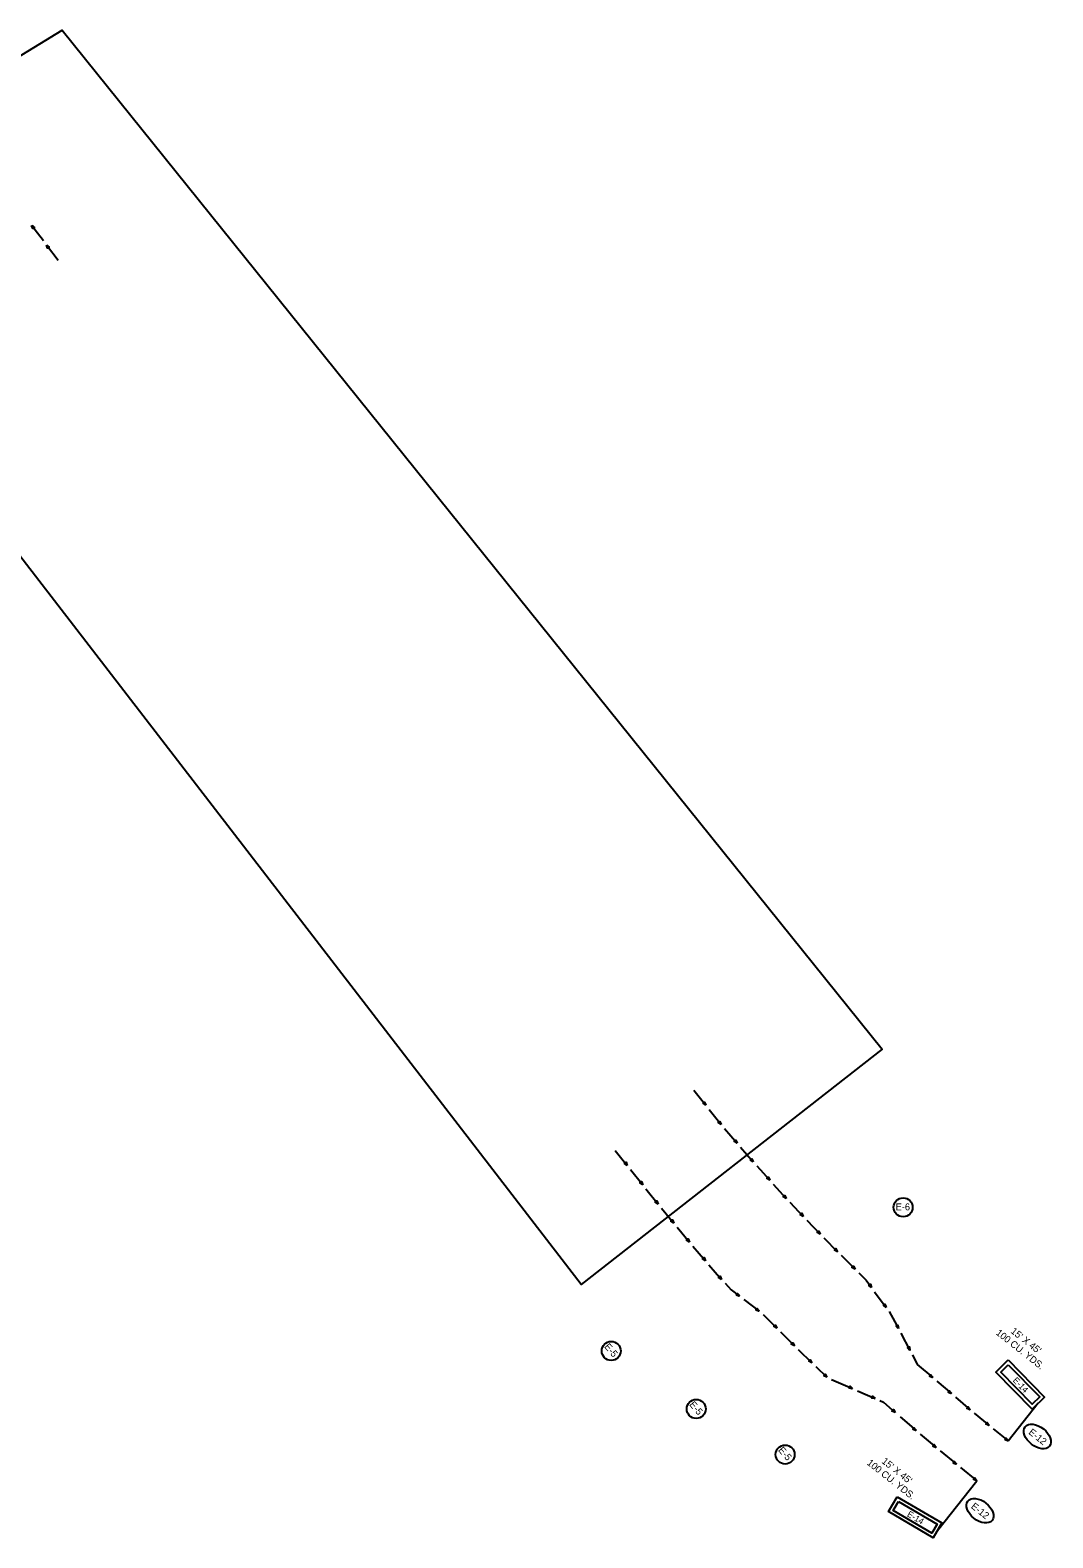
# Model space of a CAD drawing. Extents: x 881727 to 890277, y 1562105 to 1567179.
# Drawn here: x 883800 to 884689, y 1564822 to 1566132 of the extents above; entities that cross this region are included whole.
import ezdxf

# ---------------------------------------------------------------- set-up
doc = ezdxf.new("R2010")
doc.units = 0
for name, color, linetype in [('22', 7, 'Continuous'), ('R_Axis', 7, 'Continuous'), ('R_Proposed Const Limits_Cut', 7, 'Continuous'), ('R_Water', 7, 'Continuous')]:
    doc.layers.add(name, color=color, linetype=linetype)

msp = doc.modelspace()

# ---------------------------------------------------------------- linework, layer by layer
at = {"layer": '22'}
msp.add_lwpolyline([(883563.3, 1565970.3), (883827.9, 1566132), (884540.8, 1565246.7), (884279.1, 1565042.3)], close=True, dxfattribs=at)
for centre in [(884305.2, 1564984.5), (884379.1, 1564934.1), (884456.4, 1564894.5)]:
    msp.add_circle(centre, 8.26, dxfattribs=at)
at = {"layer": 'R_Proposed Const Limits_Cut'}
for p, q in [((883802.5, 1565959.7), (883801.6, 1565961.7)), ((883802.9, 1565960), (883801.7, 1565961.8)), ((883802.7, 1565959.9), (883801.7, 1565961.8)), ((883803.2, 1565960.3), (883801.8, 1565961.9)), ((883803.6, 1565960.5), (883801.9, 1565961.9)), ((883803.4, 1565960.4), (883801.9, 1565961.9)), ((883815.4, 1565942.6), (883814.5, 1565944.6)), ((883815.7, 1565942.9), (883814.6, 1565944.7)), ((883815.6, 1565942.8), (883814.6, 1565944.6)), ((883816.3, 1565943.3), (883814.7, 1565944.8)), ((883816.1, 1565943.2), (883814.7, 1565944.7)), ((883816.5, 1565943.4), (883814.8, 1565944.8)), ((884385.1, 1565199.8), (884386.8, 1565198.4)), ((884385.3, 1565199.9), (884386.9, 1565198.5)), ((884385.5, 1565200.1), (884386.9, 1565198.5)), ((884385.8, 1565200.4), (884387, 1565198.6)), ((884386, 1565200.5), (884387.1, 1565198.6)), ((884386.2, 1565200.6), (884387.1, 1565198.7)), ((884398.5, 1565183.1), (884400.2, 1565181.7)), ((884398.7, 1565183.2), (884400.3, 1565181.8)), ((884398.9, 1565183.4), (884400.3, 1565181.8)), ((884399.2, 1565183.6), (884400.4, 1565181.9)), ((884399.4, 1565183.8), (884400.4, 1565181.9)), ((884399.5, 1565183.9), (884400.5, 1565181.9)), ((884412.3, 1565166.7), (884414.1, 1565165.4)), ((884412.5, 1565166.8), (884414.1, 1565165.5)), ((884412.7, 1565167), (884414.2, 1565165.5)), ((884413, 1565167.3), (884414.3, 1565165.6)), ((884413.2, 1565167.4), (884414.3, 1565165.6)), ((884413.3, 1565167.6), (884414.4, 1565165.6)), ((884316.9, 1565147.4), (884318.6, 1565146.1)), ((884317.1, 1565147.6), (884318.6, 1565146.1)), ((884317.2, 1565147.7), (884318.7, 1565146.1)), ((884317.6, 1565148), (884318.8, 1565146.2)), ((884317.8, 1565148.1), (884318.8, 1565146.2)), ((884317.9, 1565148.2), (884318.9, 1565146.3)), ((884426.3, 1565150.5), (884428.1, 1565149.2)), ((884426.5, 1565150.6), (884428.1, 1565149.2)), ((884426.7, 1565150.8), (884428.2, 1565149.3)), ((884427, 1565151.1), (884428.2, 1565149.3)), ((884427.2, 1565151.2), (884428.3, 1565149.4)), ((884427.3, 1565151.3), (884428.3, 1565149.4)), ((884440.6, 1565134.5), (884442.4, 1565133.3)), ((884440.8, 1565134.7), (884442.4, 1565133.3)), ((884440.9, 1565134.8), (884442.5, 1565133.4)), ((884441.3, 1565135.1), (884442.6, 1565133.4)), ((884441.4, 1565135.3), (884442.6, 1565133.5)), ((884441.6, 1565135.4), (884442.7, 1565133.5)), ((884330.3, 1565130.7), (884332, 1565129.3)), ((884330.4, 1565130.8), (884332, 1565129.4)), ((884330.6, 1565131), (884332.1, 1565129.4)), ((884331, 1565131.2), (884332.1, 1565129.5)), ((884331.1, 1565131.4), (884332.2, 1565129.5)), ((884331.3, 1565131.5), (884332.2, 1565129.5)), ((884455.7, 1565119.2), (884457, 1565117.6)), ((884455.8, 1565119.4), (884457, 1565117.6)), ((884456, 1565119.5), (884457.1, 1565117.6)), ((884343.7, 1565114), (884345.4, 1565112.6)), ((884343.8, 1565114.1), (884345.4, 1565112.7)), ((884344, 1565114.3), (884345.5, 1565112.7)), ((884344.4, 1565114.5), (884345.6, 1565112.8)), ((884344.5, 1565114.7), (884345.6, 1565112.8)), ((884344.7, 1565114.8), (884345.7, 1565112.8)), ((884455, 1565118.6), (884456.8, 1565117.4)), ((884455.2, 1565118.8), (884456.8, 1565117.4)), ((884455.3, 1565118.9), (884456.9, 1565117.5)), ((884357.2, 1565097.4), (884359, 1565096.1)), ((884357.4, 1565097.5), (884359, 1565096.1)), ((884357.6, 1565097.7), (884359, 1565096.1)), ((884357.9, 1565098), (884359.1, 1565096.2)), ((884358.1, 1565098.1), (884359.2, 1565096.2)), ((884358.3, 1565098.2), (884359.2, 1565096.3)), ((884469.7, 1565103), (884471.5, 1565101.8)), ((884469.9, 1565103.2), (884471.5, 1565101.9)), ((884470, 1565103.3), (884471.6, 1565101.9)), ((884470.3, 1565103.6), (884471.7, 1565102)), ((884470.5, 1565103.8), (884471.7, 1565102)), ((884470.7, 1565104), (884471.8, 1565102.1)), ((884370.9, 1565080.9), (884372.6, 1565079.5)), ((884371, 1565081), (884372.6, 1565079.6)), ((884371.2, 1565081.2), (884372.7, 1565079.6)), ((884371.6, 1565081.4), (884372.8, 1565079.7)), ((884371.7, 1565081.6), (884372.8, 1565079.7)), ((884371.9, 1565081.7), (884372.9, 1565079.8)), ((884484.5, 1565087.5), (884486.3, 1565086.3)), ((884484.6, 1565087.7), (884486.3, 1565086.4)), ((884484.8, 1565087.8), (884486.4, 1565086.4)), ((884485.1, 1565088.1), (884486.4, 1565086.5)), ((884485.3, 1565088.3), (884486.5, 1565086.5)), ((884485.4, 1565088.4), (884486.5, 1565086.6)), ((884499.5, 1565072.3), (884501.4, 1565071.1)), ((884499.7, 1565072.5), (884501.4, 1565071.2)), ((884499.8, 1565072.6), (884501.5, 1565071.2)), ((884500.2, 1565072.9), (884501.5, 1565071.3)), ((884500.3, 1565073.1), (884501.6, 1565071.4)), ((884500.5, 1565073.2), (884501.6, 1565071.4)), ((884384.8, 1565064.6), (884386.6, 1565063.3)), ((884385, 1565064.7), (884386.6, 1565063.3)), ((884385.1, 1565064.9), (884386.6, 1565063.4)), ((884385.5, 1565065.2), (884386.7, 1565063.5)), ((884385.6, 1565065.3), (884386.8, 1565063.5)), ((884385.8, 1565065.5), (884386.8, 1565063.5)), ((884514.7, 1565057.2), (884516.5, 1565056)), ((884514.8, 1565057.3), (884516.6, 1565056.1)), ((884515, 1565057.5), (884516.6, 1565056.1)), ((884515.3, 1565057.8), (884516.7, 1565056.2)), ((884515.5, 1565057.9), (884516.7, 1565056.2)), ((884515.6, 1565058.1), (884516.8, 1565056.3)), ((884398.8, 1565048.4), (884400.6, 1565047.1)), ((884399, 1565048.5), (884400.6, 1565047.2)), ((884399.2, 1565048.7), (884400.7, 1565047.2)), ((884399.5, 1565049), (884400.8, 1565047.3)), ((884399.7, 1565049.1), (884400.8, 1565047.3)), ((884399.8, 1565049.3), (884400.8, 1565047.3)), ((884529.3, 1565041.6), (884530.9, 1565040.2)), ((884529.4, 1565041.7), (884531, 1565040.2)), ((884529.6, 1565041.9), (884531, 1565040.3)), ((884530, 1565042.1), (884531.1, 1565040.3)), ((884530.2, 1565042.3), (884531.1, 1565040.4)), ((884530.3, 1565042.4), (884531.2, 1565040.4)), ((884414.1, 1565033.2), (884416.1, 1565032.3)), ((884414.2, 1565033.4), (884416.1, 1565032.4)), ((884414.4, 1565033.6), (884416.2, 1565032.4)), ((884414.7, 1565033.9), (884416.2, 1565032.5)), ((884414.8, 1565034.1), (884416.3, 1565032.6)), ((884414.9, 1565034.3), (884416.3, 1565032.6)), ((884431.2, 1565020.3), (884433.2, 1565019.4)), ((884431.3, 1565020.5), (884433.2, 1565019.4)), ((884431.4, 1565020.6), (884433.2, 1565019.5)), ((884431.7, 1565021), (884433.3, 1565019.6)), ((884431.8, 1565021.2), (884433.3, 1565019.6)), ((884432, 1565021.3), (884433.4, 1565019.7)), ((884542, 1565024.4), (884543.6, 1565022.9)), ((884542.1, 1565024.5), (884543.7, 1565023)), ((884542.3, 1565024.6), (884543.7, 1565023)), ((884542.7, 1565024.9), (884543.8, 1565023.1)), ((884542.8, 1565025), (884543.8, 1565023.1)), ((884543, 1565025.1), (884543.9, 1565023.1)), ((884446.8, 1565005.8), (884448.6, 1565004.7)), ((884447, 1565006), (884448.7, 1565004.7)), ((884447.1, 1565006.1), (884448.7, 1565004.8)), ((884447.4, 1565006.5), (884448.8, 1565004.8)), ((884447.6, 1565006.6), (884448.8, 1565004.9)), ((884447.7, 1565006.8), (884448.9, 1565004.9)), ((884553, 1565006.2), (884554.4, 1565004.5)), ((884553.2, 1565006.3), (884554.5, 1565004.6)), ((884553.4, 1565006.4), (884554.5, 1565004.6)), ((884553.8, 1565006.6), (884554.6, 1565004.6)), ((884554, 1565006.7), (884554.7, 1565004.7)), ((884554.2, 1565006.8), (884554.7, 1565004.7)), ((884461.9, 1564990.6), (884463.7, 1564989.4)), ((884462, 1564990.8), (884463.7, 1564989.5)), ((884462.2, 1564990.9), (884463.8, 1564989.5)), ((884462.5, 1564991.2), (884463.9, 1564989.6)), ((884462.7, 1564991.4), (884463.9, 1564989.7)), ((884462.8, 1564991.5), (884464, 1564989.7)), ((884477.2, 1564975.6), (884479.1, 1564974.5)), ((884477.4, 1564975.8), (884479.1, 1564974.6)), ((884477.5, 1564976), (884479.1, 1564974.6)), ((884477.8, 1564976.3), (884479.2, 1564974.7)), ((884478, 1564976.4), (884479.3, 1564974.7)), ((884478.1, 1564976.6), (884479.3, 1564974.8)), ((884563, 1564987.2), (884564.4, 1564985.6)), ((884563.2, 1564987.3), (884564.5, 1564985.6)), ((884563.4, 1564987.4), (884564.5, 1564985.7)), ((884563.8, 1564987.7), (884564.6, 1564985.7)), ((884564, 1564987.8), (884564.7, 1564985.7)), ((884564.2, 1564987.9), (884564.7, 1564985.7)), ((884490.2, 1564963.1), (884492.1, 1564962)), ((884490.3, 1564963.3), (884492.1, 1564962)), ((884490.5, 1564963.4), (884492.1, 1564962.1)), ((884490.8, 1564963.8), (884492.2, 1564962.2)), ((884490.9, 1564963.9), (884492.2, 1564962.2)), ((884491.1, 1564964.1), (884492.3, 1564962.2)), ((884582.1, 1564962.7), (884584.1, 1564961.7)), ((884582.3, 1564962.9), (884584.1, 1564961.7)), ((884582.4, 1564963), (884584.1, 1564961.8)), ((884582.7, 1564963.4), (884584.2, 1564961.9)), ((884582.9, 1564963.5), (884584.3, 1564961.9)), ((884583, 1564963.7), (884584.3, 1564962)), ((884512.2, 1564952.4), (884514.3, 1564952)), ((884512.3, 1564952.6), (884514.3, 1564952)), ((884512.4, 1564952.8), (884514.4, 1564952.1)), ((884512.5, 1564953.2), (884514.4, 1564952.2)), ((884512.6, 1564953.4), (884514.4, 1564952.2)), ((884512.7, 1564953.6), (884514.5, 1564952.3)), ((884598.4, 1564948.7), (884600.3, 1564947.7)), ((884598.5, 1564948.9), (884600.3, 1564947.8)), ((884598.7, 1564949.1), (884600.4, 1564947.8)), ((884599, 1564949.4), (884600.5, 1564947.9)), ((884599.1, 1564949.6), (884600.5, 1564948)), ((884599.2, 1564949.7), (884600.5, 1564948)), ((884531.8, 1564943.8), (884534, 1564943.4)), ((884531.9, 1564944), (884534, 1564943.4)), ((884532, 1564944.2), (884534, 1564943.5)), ((884532.2, 1564944.8), (884534.1, 1564943.6)), ((884532.2, 1564944.6), (884534, 1564943.6)), ((884532.3, 1564945), (884534.1, 1564943.7)), ((884615.3, 1564935.6), (884616.7, 1564934)), ((884615.5, 1564935.8), (884616.8, 1564934)), ((884650.4, 1564906.3), (884676.5, 1564939.3)), ((884549.5, 1564932.5), (884551.4, 1564931.5)), ((884549.6, 1564932.7), (884551.4, 1564931.5)), ((884549.8, 1564932.8), (884551.5, 1564931.6)), ((884550.1, 1564933.2), (884551.5, 1564931.6)), ((884550.2, 1564933.3), (884551.6, 1564931.7)), ((884550.4, 1564933.5), (884551.6, 1564931.7)), ((884614.6, 1564934.8), (884616.5, 1564933.7)), ((884614.7, 1564934.9), (884616.6, 1564933.8)), ((884614.9, 1564935.1), (884616.6, 1564933.8)), ((884615.2, 1564935.4), (884616.7, 1564933.9)), ((884567.7, 1564916.6), (884569.6, 1564915.6)), ((884567.8, 1564916.8), (884569.6, 1564915.7)), ((884568, 1564917), (884569.7, 1564915.7)), ((884568.3, 1564917.3), (884569.8, 1564915.8)), ((884568.4, 1564917.5), (884569.8, 1564915.8)), ((884568.5, 1564917.6), (884569.8, 1564915.9)), ((884631.1, 1564921.1), (884633, 1564920.1)), ((884631.2, 1564921.2), (884633.1, 1564920.2)), ((884631.4, 1564921.4), (884633.1, 1564920.2)), ((884631.7, 1564921.8), (884633.2, 1564920.3)), ((884631.8, 1564921.9), (884633.2, 1564920.3)), ((884631.9, 1564922.1), (884633.3, 1564920.4)), ((884585.1, 1564901.9), (884587, 1564900.9)), ((884585.2, 1564902.1), (884587, 1564900.9)), ((884585.3, 1564902.2), (884587.1, 1564901)), ((884585.6, 1564902.6), (884587.1, 1564901.1)), ((884585.8, 1564902.7), (884587.2, 1564901.1)), ((884585.9, 1564902.9), (884587.2, 1564901.2)), ((884647.7, 1564907.6), (884649.7, 1564906.6)), ((884647.9, 1564907.7), (884649.7, 1564906.7)), ((884648, 1564907.9), (884649.7, 1564906.7)), ((884648.3, 1564908.3), (884649.8, 1564906.8)), ((884648.4, 1564908.4), (884649.9, 1564906.8)), ((884648.6, 1564908.6), (884649.9, 1564906.9)), ((884602.6, 1564887.4), (884604.6, 1564886.4)), ((884602.8, 1564887.5), (884604.6, 1564886.4)), ((884602.9, 1564887.7), (884604.6, 1564886.5)), ((884603.2, 1564888.1), (884604.7, 1564886.6)), ((884603.3, 1564888.2), (884604.8, 1564886.6)), ((884603.5, 1564888.4), (884604.8, 1564886.7)), ((884588.8, 1564828.6), (884623, 1564871.8)), ((884620.4, 1564873.1), (884622.3, 1564872.1)), ((884620.5, 1564873.2), (884622.4, 1564872.2)), ((884620.6, 1564873.4), (884622.4, 1564872.2)), ((884620.9, 1564873.8), (884622.5, 1564872.3)), ((884621.1, 1564873.9), (884622.5, 1564872.3)), ((884621.2, 1564874.1), (884622.6, 1564872.4))]:
    msp.add_line(p, q, dxfattribs=at)
for points in [[(883811.5, 1565948.9), (883801.3, 1565962.4)], [(883824.4, 1565931.8), (883814.2, 1565945.3)], [(884376.9, 1565211.2), (884387.4, 1565198)], [(884390.3, 1565194.4), (884400.8, 1565181.2)], [(884403.7, 1565177.8), (884414.7, 1565165)], [(884308.7, 1565158.8), (884319.2, 1565145.6)], [(884417.7, 1565161.5), (884428.7, 1565148.7)], [(884431.7, 1565145.4), (884443, 1565132.8)], [(884322, 1565142.1), (884332.6, 1565128.8)], [(884335.4, 1565125.4), (884346, 1565112.1)], [(884446.1, 1565129.5), (884457.4, 1565117)], [(884348.8, 1565108.6), (884359.6, 1565095.6)], [(884460.5, 1565113.7), (884472.2, 1565101.4)], [(884475.3, 1565098.2), (884486.9, 1565085.9)], [(884362.4, 1565092.1), (884373.2, 1565079.1)], [(884490.1, 1565082.7), (884502, 1565070.7)], [(884376.1, 1565075.6), (884387.2, 1565062.8)], [(884505.2, 1565067.6), (884517.2, 1565055.6)], [(884390.1, 1565059.4), (884401.2, 1565046.7)], [(884404.2, 1565043.3), (884409.6, 1565037.6)], [(884520.4, 1565052.5), (884526.9, 1565046.1)], [(884526.9, 1565046.1), (884531.5, 1565039.7)], [(884409.6, 1565037.6), (884416.8, 1565032)], [(884420.4, 1565029.3), (884433.9, 1565019.1)], [(884534.1, 1565036), (884544.2, 1565022.4)], [(884437.4, 1565016.3), (884449.3, 1565004.3)], [(884546.9, 1565018.8), (884554.9, 1565003.9)], [(884452.5, 1565001.1), (884464.4, 1564989)], [(884557, 1565000), (884564.9, 1564985)], [(884467.6, 1564985.9), (884479.7, 1564974.1)], [(884567, 1564981), (884571.3, 1564972.8)], [(884483, 1564971), (884492.7, 1564961.6)], [(884571.3, 1564972.8), (884584.8, 1564961.3)], [(884496.8, 1564959.8), (884515.1, 1564951.8)], [(884519.2, 1564950), (884534.7, 1564943.2)], [(884588.2, 1564958.4), (884601, 1564947.4)], [(884538.8, 1564941.4), (884542, 1564940)], [(884542, 1564940), (884552.1, 1564931.1)], [(884604.4, 1564944.4), (884617.2, 1564933.4)], [(884556.5, 1564927.2), (884570.3, 1564915.3)], [(884620.7, 1564930.5), (884633.7, 1564919.8)], [(884573.7, 1564912.3), (884587.7, 1564900.5)], [(884637.2, 1564916.9), (884650.4, 1564906.3)], [(884591.1, 1564897.7), (884605.3, 1564886.1)], [(884608.8, 1564883.2), (884623, 1564871.8)]]:
    msp.add_lwpolyline(points, dxfattribs=at)
for points in [[(883801.3, 1565962.4), (883803.8, 1565960.7), (883802.3, 1565959.6)], [(883814.2, 1565945.3), (883816.6, 1565943.6), (883815.2, 1565942.5)], [(884387.4, 1565198), (884385, 1565199.7), (884386.3, 1565200.8)], [(884400.8, 1565181.2), (884398.3, 1565182.9), (884399.7, 1565184)], [(884414.7, 1565165), (884412.2, 1565166.6), (884413.5, 1565167.7)], [(884319.2, 1565145.6), (884316.7, 1565147.3), (884318.1, 1565148.4)], [(884428.7, 1565148.7), (884426.2, 1565150.3), (884427.5, 1565151.5)], [(884443, 1565132.8), (884440.5, 1565134.4), (884441.8, 1565135.6)], [(884332.6, 1565128.8), (884330.1, 1565130.5), (884331.5, 1565131.6)], [(884457.4, 1565117), (884454.8, 1565118.5), (884456.1, 1565119.7)], [(884346, 1565112.1), (884343.5, 1565113.8), (884344.9, 1565115)], [(884359.6, 1565095.6), (884357.1, 1565097.2), (884358.4, 1565098.4)], [(884472.2, 1565101.4), (884469.5, 1565102.9), (884470.8, 1565104.1)], [(884373.2, 1565079.1), (884370.7, 1565080.7), (884372.1, 1565081.9)], [(884486.9, 1565085.9), (884484.3, 1565087.4), (884485.6, 1565088.6)], [(884502, 1565070.7), (884499.4, 1565072.1), (884500.6, 1565073.4)], [(884387.2, 1565062.8), (884384.6, 1565064.4), (884386, 1565065.6)], [(884517.2, 1565055.6), (884514.5, 1565057), (884515.8, 1565058.3)], [(884401.2, 1565046.7), (884398.6, 1565048.2), (884400, 1565049.4)], [(884531.5, 1565039.7), (884529.1, 1565041.5), (884530.5, 1565042.5)], [(884416.8, 1565032), (884414, 1565033.1), (884415.1, 1565034.5)], [(884433.9, 1565019.1), (884431, 1565020.1), (884432.1, 1565021.5)], [(884544.2, 1565022.4), (884541.8, 1565024.2), (884543.2, 1565025.3)], [(884449.3, 1565004.3), (884446.6, 1565005.7), (884447.9, 1565006.9)], [(884554.9, 1565003.9), (884552.8, 1565006.1), (884554.3, 1565006.9)], [(884464.4, 1564989), (884461.7, 1564990.5), (884463, 1564991.7)], [(884479.7, 1564974.1), (884477, 1564975.5), (884478.3, 1564976.8)], [(884564.9, 1564985), (884562.8, 1564987.1), (884564.4, 1564988)], [(884492.7, 1564961.6), (884490, 1564963), (884491.3, 1564964.2)], [(884584.8, 1564961.3), (884582, 1564962.5), (884583.2, 1564963.9)], [(884515.1, 1564951.8), (884512.1, 1564952.2), (884512.8, 1564953.8)], [(884601, 1564947.4), (884598.2, 1564948.6), (884599.4, 1564949.9)], [(884534.7, 1564943.2), (884531.7, 1564943.6), (884532.4, 1564945.2)], [(884617.2, 1564933.4), (884614.5, 1564934.6), (884615.6, 1564935.9)], [(884552.1, 1564931.1), (884549.3, 1564932.3), (884550.5, 1564933.7)], [(884570.3, 1564915.3), (884567.5, 1564916.5), (884568.7, 1564917.8)], [(884633.7, 1564919.8), (884630.9, 1564920.9), (884632.1, 1564922.3)], [(884587.7, 1564900.5), (884584.9, 1564901.7), (884586.1, 1564903.1)], [(884650.4, 1564906.3), (884647.6, 1564907.4), (884648.7, 1564908.8)], [(884605.3, 1564886.1), (884602.5, 1564887.2), (884603.6, 1564888.6)], [(884623, 1564871.8), (884620.2, 1564872.9), (884621.3, 1564874.3)]]:
    msp.add_lwpolyline(points, close=True, dxfattribs=at)
for centre in [(884675.7, 1564910.2), (884625.8, 1564845.7)]:
    msp.add_ellipse(centre, major_axis=(10.6, -8.4), ratio=0.622952, dxfattribs=at)
at = {"layer": 'R_Water'}
for points in [[(884650.4, 1564976.7), (884681.9, 1564944.5), (884671.2, 1564934), (884639.7, 1564966.2)], [(884650.4, 1564972.5), (884677.7, 1564944.6), (884671.2, 1564938.3), (884644, 1564966.2)], [(884553.8, 1564857.9), (884592.6, 1564835.1), (884585, 1564822.1), (884546.2, 1564844.9)], [(884554.9, 1564853.7), (884588.5, 1564834), (884583.9, 1564826.2), (884550.3, 1564846)]]:
    msp.add_lwpolyline(points, close=True, dxfattribs=at)
for centre in [(884559, 1565109.3), (884305.2, 1564984.5), (884379.1, 1564934.1), (884456.4, 1564894.5)]:
    msp.add_circle(centre, 8.26, dxfattribs=at)

# ---------------------------------------------------------------- texts
at = {"layer": 'R_Axis'}
for s, p in [('100 CU. YDS.', (884639.1, 1564999.3)), ("15' X 45'", (884652, 1565000.7)), ('100 CU. YDS.', (884527, 1564886.3)), ("15' X 45'", (884539.8, 1564887.7))]:
    msp.add_text(s, height=6, rotation=321.5971, dxfattribs=at).set_placement(p)
at = {"layer": 'R_Proposed Const Limits_Cut'}
for p in [(884667.5, 1564912.9), (884617.5, 1564848.5)]:
    msp.add_text('E-12', height=6, rotation=321.5971, dxfattribs=at).set_placement(p)
at = {"layer": 'R_Water'}
msp.add_text('E-6 ', height=6, dxfattribs=at).set_placement((884552.5, 1565106.7))
for s, height, rotation, p in [('E-5 ', 6, 310.5862, (884298.8, 1564988)), ('E-14', 5.4, 314.3806, (884653.9, 1564958.5)), ('E-5 ', 6, 310.5862, (884372.7, 1564937.7)), ('E-5 ', 6, 310.5862, (884450, 1564898.1)), ('E-14', 5.4, 329.5832, (884561.9, 1564841.2))]:
    msp.add_text(s, height=height, rotation=rotation, dxfattribs=at).set_placement(p)

doc.saveas('drawing.dxf')
